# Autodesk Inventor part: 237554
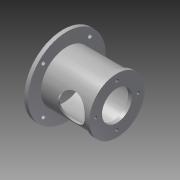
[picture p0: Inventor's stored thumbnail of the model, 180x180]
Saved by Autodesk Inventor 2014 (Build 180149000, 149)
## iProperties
Shininess: 20.0
Length Units: 11272
Angle Units: 11279
Time Units: 11290
Mass Units: 11286
Length Display Precision: 3
Angle Display Precision: 2
Company: Autodesk, Inc.
Created: 2002-07
Part Number: 237554
Material: Steel, Mild
Description: PUMP MOUNT
Document SubType Name: Modeling
Designer: Autodesk, Inc.
Density: 7.86 g/cm^3
Mass: 17316.4 g
Surface Area: 4484.25 cm^2
Volume: 2203.1 cm^3
Appearance: Steel
Density: 0.0
Volumn: 0.0
Area: 0.0
PropertySet Name: Model Information
Control State: 0
Master: False
Checked Out: False
Last Check In By: JT
Last Check In Date: 2003-06-20
Title: PUMP MOUNT
Author: Autodesk, Inc.
Comments: MODEL IS SIMPLY REPRESENTATION OF THE PUMP MOUNT.  CHECK DIMENSIONAL ACCURACY IF IT'S CRITICAL.
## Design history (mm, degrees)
sketch "Sketch1"
  geometry: L1 (83.82, 63.5)-(67.945, 63.5); L2 (67.945, 63.5)-(67.945, 101.6); L3 (67.945, 101.6)-(-141.605, 101.6); L4 (-141.605, 101.6)-(-141.605, 127); L5 (-141.605, 127)-(-144.78, 127); L6 (-144.78, 127)-(-144.78, 165.1); L7 (-144.78, 165.1)-(-128.905, 165.1); L8 (-128.905, 165.1)-(-128.905, 109.537); L9 (-128.905, 109.537)-(67.945, 109.538); L10 (67.945, 109.538)-(67.945, 117.475); L11 (67.945, 117.475)-(83.82, 117.475); L12 (83.82, 117.475)-(83.82, 63.5); L13 (0, 0)-(-33.82, 0)
  constraints: 26 end point, 9 parallel, 2 perpendicular, 1 collinear, 1 horizontal, 1 vertical alignment
  dimensions: "d3" = 83.82 distance from line of L12 L13.start; "d4" = 228.6 distance between parallel lines of L6 L12; "d5" = 330.2 diameter of L7 L13; "d6" = 203.2 diameter of L3 L13; "d7" = 219.075 diameter of L9 L13; "d8" = 15.875 distance between parallel lines of L6 L8; "d9" = 234.95 diameter of L11 L13; "d10" = 127 diameter of L1 L13; "d11" = 15.875 distance between parallel lines of L2 L12; "d12" = 38.1 distance of L5.end L6.end; "d13" = 3.175 distance between parallel lines of L6 L4
revolve "Revolution1" sketch "Sketch1" stored, may be unused: angle "d14" = 90 deg
sketch "Sketch2"
  geometry: C1 r 57.15 at (0, 0); 1 further point
  constraints: 1 centre point, 1 coincident
  dimensions: "d15" = 114.3 diameter of C1
extrude "Extrusion2" cut sketch "Sketch2" stored distance "d16" = 25.4; taper "d17" = 0 deg
sketch "Sketch3"
  geometry: L1 (-98.783, 98.783)-(0, 0); L2 (0, 0)-(-139.7, 0); C1 r 127 at (0, 0) reference; A1 r 139.7 centre (0, 0) between (-98.783, -98.783) and (-98.783, 98.783); 2 further points
  constraints: 4 end point, 4 point on circle, 2 horizontal alignment, 2 vertical alignment, 1 centre point, 1 coincident, 1 horizontal
  dimensions: "d18" = 279.4 diameter of A1; "d19" = 45 deg angle of L1 L2
hole "Hole1" sketch "Sketch3" at (-98.783, 98.783), (98.783, 98.783), (98.783, -98.783), (-98.783, -98.783) diameter "d20" = 16.66875; stored, may be unused: countersink angle "d24" = 82 deg, drill point angle "d26" = 118 deg; dims "d21" = 12.7, "d22" = 9.525, "d23" = 6.35, "d25" = 19.05
sketch "Sketch4"
  geometry: C1 r 63.5 at (0, 0) reference; C2 r 117.475 at (0, 0) reference; A1 r 90.487 centre (0, 0) between (-90.487, 0) and (0, 90.487); 2 further points
  constraints: 4 point on circle, 2 horizontal alignment, 2 vertical alignment, 1 centre point, 1 coincident
  dimensions: "d27" = 180.975 diameter of A1
hole "Hole2" sketch "Sketch4" at (0, 90.487), (0, -90.487), (-90.487, 0), (90.487, 0) diameter "d28" = 13.3858; stored, may be unused: countersink angle "d32" = 82 deg, drill point angle "d34" = 118 deg; dims "d29" = 12.7, "d30" = 9.525, "d31" = 6.35, "d33" = 19.05
body "Solid1"
